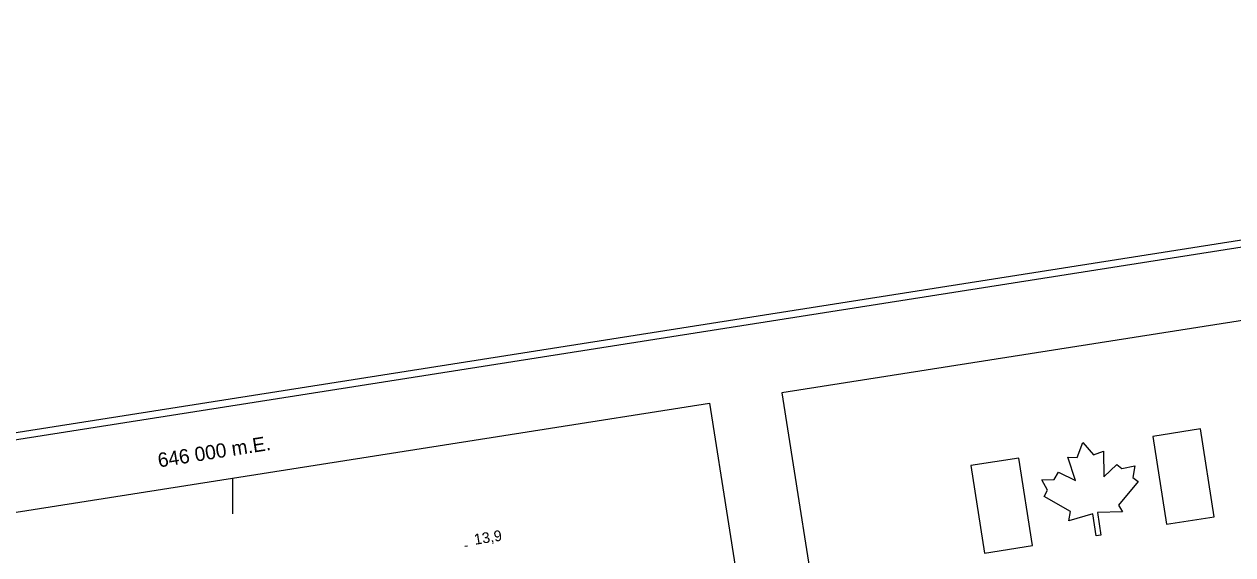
# Model space of a CAD drawing. Extents: x 643342 to 646936, y 5873857 to 5876103.
# Drawn here: x 645941.9 to 646279.3, y 5875954.3 to 5876102.6 of the extents above; entities that cross this region are included whole.
import ezdxf

# ---------------------------------------------------------------- set-up
doc = ezdxf.new("R2010")
doc.units = 0
for name, color, linetype in [('Niveau 3', 7, 'Continuous'), ('Niveau 60', 7, 'Continuous'), ('Niveau 61', 7, 'Continuous'), ('Niveau 63', 7, 'Continuous')]:
    doc.layers.add(name, color=color, linetype=linetype)

msp = doc.modelspace()

# ---------------------------------------------------------------- linework, layer by layer
at = {"layer": 'Niveau 3'}
msp.add_line((646064.87, 5875956.67), (646065.66, 5875956.8), dxfattribs=at)
at = {"layer": 'Niveau 60'}
msp.add_line((646000, 5875975.71), (646000, 5875965.71), dxfattribs=at)
for points in [[(643342.09, 5875579.85), (646664.86, 5876102.57), (646935.9, 5874379.74), (643613.15, 5873856.99), (643342.1, 5875579.83)], [(643342.09, 5875579.85), (646664.86, 5876102.57), (646935.9, 5874379.74), (643613.15, 5873856.99), (643342.1, 5875579.83)], [(643342.09, 5875579.85), (646664.86, 5876102.57), (646935.9, 5874379.74), (643613.15, 5873856.99), (643342.1, 5875579.83)], [(643344.38, 5875578.18), (646663.19, 5876100.29), (646933.6, 5874381.38), (643614.81, 5873859.28), (643344.38, 5875578.18)], [(643344.38, 5875578.18), (646663.19, 5876100.29), (646933.6, 5874381.38), (643614.81, 5873859.28), (643344.38, 5875578.18)], [(643344.38, 5875578.18), (646663.19, 5876100.29), (646933.6, 5874381.38), (643614.81, 5873859.28), (643344.38, 5875578.18)], [(646417.19, 5874320.42), (646911.1, 5874398.11), (646647.07, 5876077.14), (646153.42, 5875999.51), (646417.52, 5874320.47)]]:
    msp.add_lwpolyline(points, dxfattribs=at)
msp.add_lwpolyline([(643367.26, 5875561.52), (646133.22, 5875996.67), (646397.42, 5874317.29), (643631.46, 5873882.15)], close=True, dxfattribs=at)
at = {"layer": 'Niveau 63'}
for points in [[(646260.82, 5875962.87), (646274.16, 5875964.95), (646270.34, 5875989.48), (646256.98, 5875987.36)], [(646241.19, 5875959.64), (646240.24, 5875965.75), (646233.52, 5875963.8), (646234.04, 5875966.36), (646226.65, 5875970.57), (646227.61, 5875972.35), (646226.04, 5875975.2), (646229.44, 5875975.34), (646230.63, 5875977.34), (646235.37, 5875975.02), (646233.25, 5875981.55), (646235.89, 5875981.47), (646237.46, 5875985.7), (646240.43, 5875982.24), (646243.22, 5875983.21), (646243.3, 5875976.04), (646246.96, 5875979.53), (646248.37, 5875978.45), (646251.99, 5875979.14), (646251.47, 5875975.87), (646252.88, 5875974.75), (646247.42, 5875968.14), (646248.56, 5875966.26), (646241.57, 5875966.11), (646242.53, 5875959.76)], [(646241.19, 5875959.64), (646240.24, 5875965.75), (646233.52, 5875963.8), (646234.04, 5875966.36), (646226.65, 5875970.57), (646227.61, 5875972.35), (646226.04, 5875975.2), (646229.44, 5875975.34), (646230.63, 5875977.34), (646235.37, 5875975.02), (646233.25, 5875981.55), (646235.89, 5875981.47), (646237.46, 5875985.7), (646240.43, 5875982.24), (646243.22, 5875983.21), (646243.3, 5875976.04), (646246.96, 5875979.53), (646248.37, 5875978.45), (646251.99, 5875979.14), (646251.47, 5875975.87), (646252.88, 5875974.75), (646247.42, 5875968.14), (646248.56, 5875966.26), (646241.57, 5875966.11), (646242.53, 5875959.76)], [(646219.56, 5875981.34), (646206.23, 5875979.26), (646210.04, 5875954.74), (646223.42, 5875956.85)]]:
    msp.add_lwpolyline(points, close=True, dxfattribs=at)

# ---------------------------------------------------------------- texts
at = {"layer": 'Niveau 3'}
msp.add_text('13,9 ', height=3, rotation=8.9405, dxfattribs=at).set_placement((646067.72, 5875957.08))
at = {"layer": 'Niveau 61'}
msp.add_text('646 000 m.E.', height=3.9998, rotation=8.9407, dxfattribs=at).set_placement((645979.49, 5875978.69))

doc.saveas('drawing.dxf')
